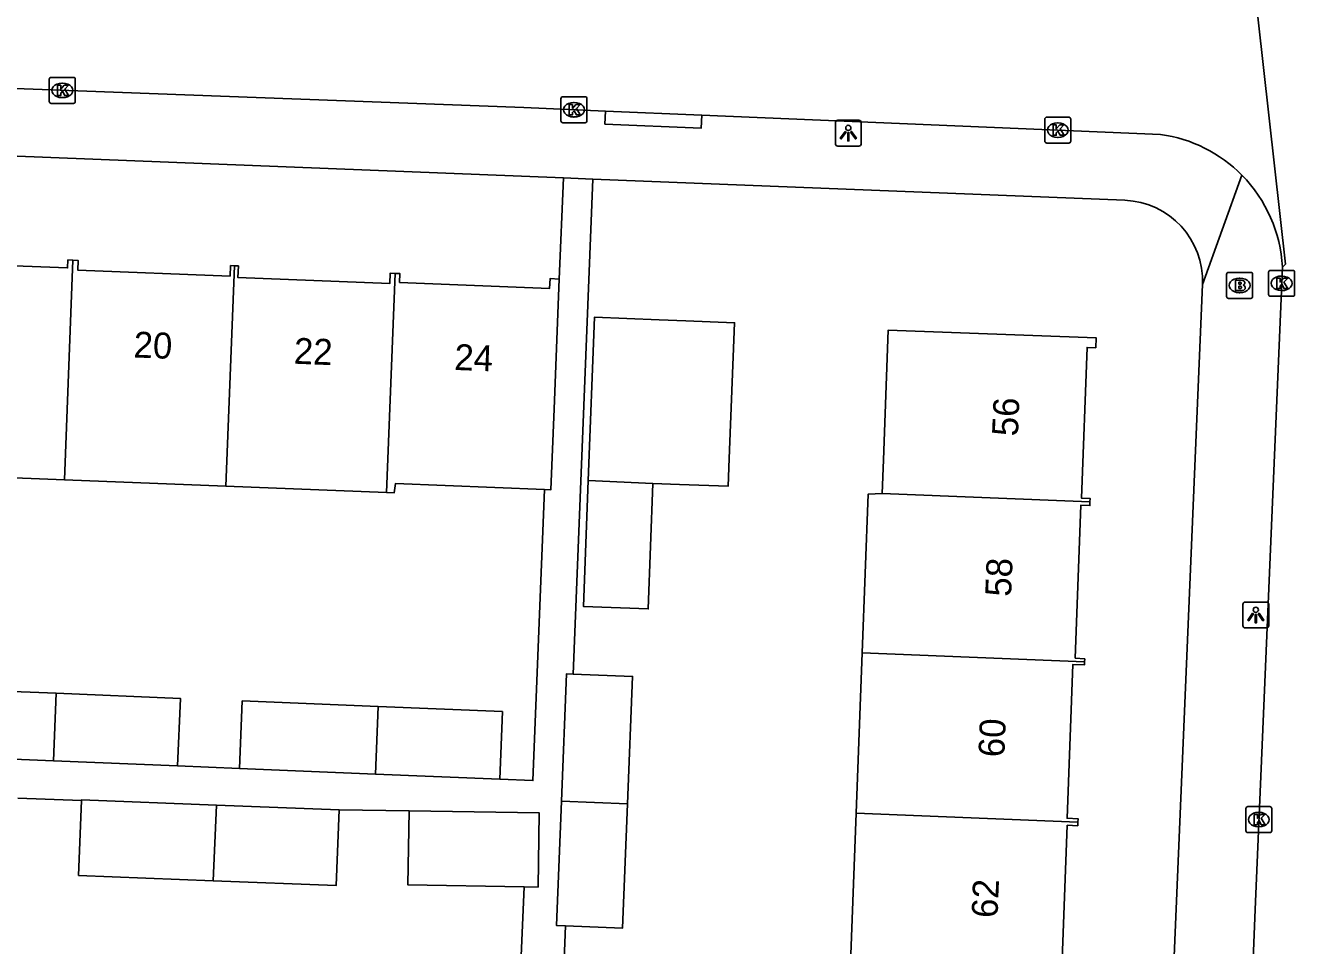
# Model space of a CAD drawing. Extents: x 160077 to 160945, y 386481 to 387498.
# Drawn here: x 160763.56 to 160812.48, y 386635.24 to 386670.7 of the extents above; entities that cross this region are included whole.
import ezdxf

# ---------------------------------------------------------------- set-up
doc = ezdxf.new("R2010")
doc.units = 0
for name, color, linetype in [('IMGEO_Brandkraan', 7, 'Continuous'), ('IMGEO_Kolk', 7, 'Continuous'), ('IMGEO_Lichtpunt', 7, 'Continuous'), ('IMGEO_Pand', 7, 'Continuous'), ('IMGEO_Pand_nummerreeks', 7, 'Continuous'), ('IMGEO_Rijbaan_lokaal_open', 7, 'Continuous'), ('IMGEO_Voetpad_open', 7, 'Continuous')]:
    doc.layers.add(name, color=color, linetype=linetype)

msp = doc.modelspace()

# ---------------------------------------------------------------- linework, layer by layer
at = {"layer": 'IMGEO_Brandkraan'}
for p, q in [((160809.863, 386660.258), (160809.863, 386661.11)), ((160809.938, 386661.184), (160810.79, 386661.184)), ((160810.864, 386661.11), (160810.864, 386660.258)), ((160810.351, 386660.964), (160810.376, 386660.964)), ((160810.79, 386660.184), (160809.938, 386660.184)), ((160810.374, 386660.404), (160810.349, 386660.404))]:
    msp.add_line(p, q, dxfattribs=at)
for points in [[(160809.863, 386660.258), (160809.863, 386661.11)], [(160809.938, 386661.184), (160810.79, 386661.184)], [(160810.864, 386661.11), (160810.864, 386660.258)], [(160810.211, 386660.884), (160810.211, 386660.484), (160810.424, 386660.484)], [(160810.442, 386660.884), (160810.211, 386660.884)], [(160810.39, 386660.803), (160810.336, 386660.803), (160810.336, 386660.727)], [(160810.336, 386660.727), (160810.389, 386660.727)], [(160810.398, 386660.651), (160810.336, 386660.651), (160810.336, 386660.57)], [(160810.336, 386660.57), (160810.398, 386660.57)], [(160810.79, 386660.184), (160809.938, 386660.184)]]:
    msp.add_lwpolyline(points, dxfattribs=at)
for centre, radius, start, end in [((160809.94, 386661.108), 0.0765, 91.552, 178.448), ((160809.94, 386661.108), 0.0765, 91.552, 178.448), ((160810.788, 386661.108), 0.0765, 1.552, 88.448), ((160810.788, 386661.108), 0.0765, 1.552, 88.448), ((160810.391, 386660.765), 0.0379, 267.8285, 90.9355), ((160810.399, 386660.61), 0.0404, 269.8759, 90.5077), ((160810.43, 386660.735), 0.251, 268.6676, 293.5347), ((160810.446, 386660.739), 0.145, 59.4692, 91.5367), ((160810.471, 386660.786), 0.0922, 285.5137, 58.1501), ((160810.476, 386660.594), 0.105, 301.3115, 78.989), ((160809.94, 386660.26), 0.0765, 181.552, 268.448), ((160809.94, 386660.26), 0.0765, 181.552, 268.448), ((160810.788, 386660.26), 0.0765, 271.552, 358.448), ((160810.788, 386660.26), 0.0765, 271.552, 358.448)]:
    msp.add_arc(centre, radius, start, end, dxfattribs=at)
for centre, major_axis, ratio, start_param, end_param in [((160810.35, 386660.684), (-0.387, 0.002), 0.722429, 4.712389, 7.853982), ((160810.375, 386660.684), (-0.39, 0.002), 0.717154, 1.570796, 4.712389)]:
    msp.add_ellipse(centre, major_axis=major_axis, ratio=ratio, start_param=start_param, end_param=end_param, dxfattribs=at)
at = {"layer": 'IMGEO_Kolk'}
for p, q in [((160764.486, 386667.773), (160764.486, 386668.625)), ((160764.561, 386668.699), (160765.413, 386668.699)), ((160764.974, 386668.479), (160764.999, 386668.479)), ((160765.487, 386668.625), (160765.487, 386667.773)), ((160764.997, 386667.919), (160764.972, 386667.919)), ((160784.207, 386667.027), (160784.207, 386667.879)), ((160784.282, 386667.953), (160785.134, 386667.953)), ((160785.208, 386667.879), (160785.208, 386667.027)), ((160765.413, 386667.699), (160764.561, 386667.699)), ((160784.695, 386667.733), (160784.72, 386667.733)), ((160785.134, 386666.953), (160784.282, 386666.953)), ((160784.718, 386667.173), (160784.693, 386667.173)), ((160802.855, 386666.241), (160802.855, 386667.093)), ((160802.93, 386667.167), (160803.782, 386667.167)), ((160803.343, 386666.947), (160803.368, 386666.947)), ((160803.856, 386667.093), (160803.856, 386666.241)), ((160803.366, 386666.387), (160803.341, 386666.387)), ((160803.782, 386666.167), (160802.93, 386666.167)), ((160811.482, 386660.338), (160811.482, 386661.19)), ((160811.557, 386661.264), (160812.409, 386661.264)), ((160811.97, 386661.044), (160811.995, 386661.044)), ((160812.483, 386661.19), (160812.483, 386660.338)), ((160812.409, 386660.264), (160811.557, 386660.264)), ((160811.993, 386660.484), (160811.968, 386660.484)), ((160810.603, 386639.674), (160810.603, 386640.526)), ((160810.678, 386640.6), (160811.53, 386640.6)), ((160811.604, 386640.526), (160811.604, 386639.674)), ((160811.091, 386640.38), (160811.116, 386640.38)), ((160811.53, 386639.6), (160810.678, 386639.6)), ((160811.114, 386639.82), (160811.089, 386639.82))]:
    msp.add_line(p, q, dxfattribs=at)
for points in [[(160764.486, 386667.773), (160764.486, 386668.625)], [(160764.561, 386668.699), (160765.413, 386668.699)], [(160764.807, 386668.399), (160764.93, 386668.399), (160764.93, 386668.248), (160765.06, 386668.399), (160765.224, 386668.399), (160765.078, 386668.248), (160765.231, 386667.999), (160765.079, 386667.999), (160764.994, 386668.163), (160764.93, 386668.096), (160764.93, 386667.999), (160764.807, 386667.999), (160764.807, 386668.399)], [(160765.487, 386668.625), (160765.487, 386667.773)], [(160784.207, 386667.027), (160784.207, 386667.879)], [(160784.282, 386667.953), (160785.134, 386667.953)], [(160785.208, 386667.879), (160785.208, 386667.027)], [(160765.413, 386667.699), (160764.561, 386667.699)], [(160784.528, 386667.653), (160784.651, 386667.653), (160784.651, 386667.502), (160784.781, 386667.653), (160784.945, 386667.653), (160784.799, 386667.502), (160784.952, 386667.253), (160784.8, 386667.253), (160784.715, 386667.417), (160784.651, 386667.35), (160784.651, 386667.253), (160784.528, 386667.253), (160784.528, 386667.653)], [(160785.134, 386666.953), (160784.282, 386666.953)], [(160802.855, 386666.241), (160802.855, 386667.093)], [(160802.93, 386667.167), (160803.782, 386667.167)], [(160803.176, 386666.867), (160803.299, 386666.867), (160803.299, 386666.716), (160803.429, 386666.867), (160803.593, 386666.867), (160803.447, 386666.716), (160803.6, 386666.467), (160803.448, 386666.467), (160803.363, 386666.631), (160803.299, 386666.564), (160803.299, 386666.467), (160803.176, 386666.467), (160803.176, 386666.867)], [(160803.856, 386667.093), (160803.856, 386666.241)], [(160803.782, 386666.167), (160802.93, 386666.167)], [(160811.482, 386660.338), (160811.482, 386661.19)], [(160811.557, 386661.264), (160812.409, 386661.264)], [(160812.483, 386661.19), (160812.483, 386660.338)], [(160811.803, 386660.964), (160811.926, 386660.964), (160811.926, 386660.813), (160812.056, 386660.964), (160812.22, 386660.964), (160812.074, 386660.813), (160812.227, 386660.564), (160812.075, 386660.564), (160811.99, 386660.728), (160811.926, 386660.661), (160811.926, 386660.564), (160811.803, 386660.564), (160811.803, 386660.964)], [(160812.409, 386660.264), (160811.557, 386660.264)], [(160810.603, 386639.674), (160810.603, 386640.526)], [(160810.678, 386640.6), (160811.53, 386640.6)], [(160811.604, 386640.526), (160811.604, 386639.674)], [(160810.924, 386640.3), (160811.047, 386640.3), (160811.047, 386640.149), (160811.177, 386640.3), (160811.341, 386640.3), (160811.195, 386640.149), (160811.348, 386639.9), (160811.196, 386639.9), (160811.111, 386640.064), (160811.047, 386639.997), (160811.047, 386639.9), (160810.924, 386639.9), (160810.924, 386640.3)], [(160811.53, 386639.6), (160810.678, 386639.6)]]:
    msp.add_lwpolyline(points, dxfattribs=at)
for centre, start, end in [((160764.563, 386668.623), 91.552, 178.448), ((160764.563, 386668.623), 91.552, 178.448), ((160765.411, 386668.623), 1.552, 88.448), ((160765.411, 386668.623), 1.552, 88.448), ((160784.284, 386667.877), 91.552, 178.448), ((160784.284, 386667.877), 91.552, 178.448), ((160785.132, 386667.877), 1.552, 88.448), ((160785.132, 386667.877), 1.552, 88.448), ((160764.563, 386667.775), 181.552, 268.448), ((160764.563, 386667.775), 181.552, 268.448), ((160765.411, 386667.775), 271.552, 358.448), ((160765.411, 386667.775), 271.552, 358.448), ((160784.284, 386667.029), 181.552, 268.448), ((160784.284, 386667.029), 181.552, 268.448), ((160785.132, 386667.029), 271.552, 358.448), ((160785.132, 386667.029), 271.552, 358.448), ((160802.932, 386667.091), 91.552, 178.448), ((160802.932, 386667.091), 91.552, 178.448), ((160803.78, 386667.091), 1.552, 88.448), ((160803.78, 386667.091), 1.552, 88.448), ((160802.932, 386666.243), 181.552, 268.448), ((160802.932, 386666.243), 181.552, 268.448), ((160803.78, 386666.243), 271.552, 358.448), ((160803.78, 386666.243), 271.552, 358.448), ((160811.559, 386661.188), 91.552, 178.448), ((160811.559, 386661.188), 91.552, 178.448), ((160812.407, 386661.188), 1.552, 88.448), ((160812.407, 386661.188), 1.552, 88.448), ((160811.559, 386660.34), 181.552, 268.448), ((160811.559, 386660.34), 181.552, 268.448), ((160812.407, 386660.34), 271.552, 358.448), ((160812.407, 386660.34), 271.552, 358.448), ((160810.68, 386640.524), 91.552, 178.448), ((160810.68, 386640.524), 91.552, 178.448), ((160811.528, 386640.524), 1.552, 88.448), ((160811.528, 386640.524), 1.552, 88.448), ((160810.68, 386639.676), 181.552, 268.448), ((160810.68, 386639.676), 181.552, 268.448), ((160811.528, 386639.676), 271.552, 358.448), ((160811.528, 386639.676), 271.552, 358.448)]:
    msp.add_arc(centre, 0.0765, start, end, dxfattribs=at)
for centre, major_axis, ratio, start_param, end_param in [((160764.973, 386668.199), (-0.387, 0.002), 0.722429, 4.712389, 7.853982), ((160764.998, 386668.199), (-0.39, 0.002), 0.717154, 1.570796, 4.712389), ((160784.694, 386667.453), (-0.387, 0.002), 0.722429, 4.712389, 7.853982), ((160784.719, 386667.453), (-0.39, 0.002), 0.717154, 1.570796, 4.712389), ((160803.342, 386666.667), (-0.387, 0.002), 0.722429, 4.712389, 7.853982), ((160803.367, 386666.667), (-0.39, 0.002), 0.717154, 1.570796, 4.712389), ((160811.969, 386660.764), (-0.387, 0.002), 0.722429, 4.712389, 7.853982), ((160811.994, 386660.764), (-0.39, 0.002), 0.717154, 1.570796, 4.712389), ((160811.09, 386640.1), (-0.387, 0.002), 0.722429, 4.712389, 7.853982), ((160811.115, 386640.1), (-0.39, 0.002), 0.717154, 1.570796, 4.712389)]:
    msp.add_ellipse(centre, major_axis=major_axis, ratio=ratio, start_param=start_param, end_param=end_param, dxfattribs=at)
at = {"layer": 'IMGEO_Lichtpunt'}
for p, q in [((160794.783, 386666.955), (160794.783, 386666.148)), ((160794.783, 386666.955), (160794.783, 386666.148)), ((160795.685, 386667.05), (160794.877, 386667.05)), ((160795.685, 386667.05), (160794.877, 386667.05)), ((160795.779, 386666.148), (160795.779, 386666.955)), ((160795.779, 386666.148), (160795.779, 386666.955)), ((160794.877, 386666.054), (160795.685, 386666.054)), ((160794.877, 386666.054), (160795.685, 386666.054)), ((160810.489, 386648.387), (160810.489, 386647.58)), ((160810.489, 386648.387), (160810.489, 386647.58)), ((160811.391, 386648.482), (160810.583, 386648.482)), ((160811.391, 386648.482), (160810.583, 386648.482)), ((160811.485, 386647.58), (160811.485, 386648.387)), ((160811.485, 386647.58), (160811.485, 386648.387)), ((160810.583, 386647.486), (160811.391, 386647.486)), ((160810.583, 386647.486), (160811.391, 386647.486))]:
    msp.add_line(p, q, dxfattribs=at)
for points in [[(160795.157, 386666.619), (160795.196, 386666.591), (160795.008, 386666.329), (160794.97, 386666.356), (160795.157, 386666.619)], [(160795.259, 386666.571), (160795.306, 386666.571), (160795.306, 386666.249), (160795.259, 386666.249), (160795.259, 386666.571)], [(160795.369, 386666.591), (160795.407, 386666.618), (160795.594, 386666.356), (160795.555, 386666.328), (160795.369, 386666.591)], [(160810.863, 386648.051), (160810.902, 386648.023), (160810.714, 386647.761), (160810.676, 386647.788), (160810.863, 386648.051)], [(160810.965, 386648.003), (160811.012, 386648.003), (160811.012, 386647.681), (160810.965, 386647.681), (160810.965, 386648.003)], [(160811.075, 386648.023), (160811.113, 386648.05), (160811.3, 386647.788), (160811.261, 386647.76), (160811.075, 386648.023)]]:
    msp.add_lwpolyline(points, dxfattribs=at)
for centre in [(160795.282, 386666.753), (160810.988, 386648.185)]:
    msp.add_circle(centre, 0.0994, dxfattribs=at)
for centre, start, end in [((160794.877, 386666.955), 90, 180), ((160794.877, 386666.955), 90, 180), ((160795.685, 386666.955), 0, 90), ((160795.685, 386666.955), 0, 90), ((160794.877, 386666.148), 180, 270), ((160794.877, 386666.148), 180, 270), ((160795.685, 386666.148), 270, 0), ((160795.685, 386666.148), 270, 360), ((160810.583, 386648.387), 90, 180), ((160810.583, 386648.387), 90, 180), ((160811.391, 386648.387), 0, 90), ((160811.391, 386648.387), 0, 90), ((160810.583, 386647.58), 180, 270), ((160810.583, 386647.58), 180, 270), ((160811.391, 386647.58), 270, 0), ((160811.391, 386647.58), 270, 360)]:
    msp.add_arc(centre, 0.0946, start, end, dxfattribs=at)
at = {"layer": 'IMGEO_Pand'}
for points in [[(160759.252, 386661.87), (160759.369, 386661.869), (160759.369, 386661.58), (160765.188, 386661.36), (160765.2, 386661.664), (160765.398, 386661.657)], [(160765.398, 386661.657), (160765.07, 386653.196)], [(160765.398, 386661.657), (160765.597, 386661.649), (160765.583, 386661.277), (160771.454, 386661.043), (160771.47, 386661.448), (160771.622, 386661.442)], [(160771.293, 386652.951), (160771.622, 386661.442)], [(160771.622, 386661.442), (160771.775, 386661.435), (160771.758, 386660.986), (160777.607, 386660.753), (160777.623, 386661.153), (160777.812, 386661.146)], [(160777.812, 386661.146), (160777.485, 386652.707)], [(160784.143, 386660.93), (160783.785, 386660.944), (160783.77, 386660.568), (160777.988, 386660.799), (160778.002, 386661.138), (160777.812, 386661.146)], [(160783.572, 386652.817), (160783.82, 386652.807), (160783.944, 386655.934), (160784.143, 386660.93)], [(160785.257, 386653.161), (160785.496, 386659.456), (160787.992, 386659.357), (160789.023, 386659.316), (160790.896, 386659.242), (160790.688, 386654.011), (160790.646, 386652.946), (160788.773, 386653.018), (160787.753, 386653.057)], [(160796.583, 386652.663), (160796.632, 386653.966), (160796.822, 386658.962), (160804.836, 386658.658), (160804.821, 386658.281), (160804.486, 386658.294), (160804.266, 386652.489), (160804.603, 386652.476), (160804.597, 386652.338)], [(160758.926, 386653.439), (160765.07, 386653.196)], [(160765.07, 386653.196), (160771.293, 386652.951)], [(160787.753, 386653.057), (160787.569, 386648.216), (160785.073, 386648.315), (160785.257, 386653.161)], [(160785.257, 386653.161), (160787.753, 386653.057)], [(160771.293, 386652.951), (160777.485, 386652.707)], [(160777.485, 386652.707), (160777.779, 386652.695), (160777.825, 386653.046), (160783.572, 386652.817)], [(160795.818, 386646.524), (160796.05, 386652.641), (160796.583, 386652.663)], [(160804.597, 386652.338), (160796.583, 386652.663)], [(160804.597, 386652.338), (160804.592, 386652.201), (160804.241, 386652.214), (160804.026, 386646.323), (160804.395, 386646.292), (160804.39, 386646.178)], [(160764.751, 386644.969), (160762.383, 386645.067), (160762.43, 386646.212), (160759.919, 386646.316), (160759.872, 386645.17), (160759.511, 386645.185), (160759.404, 386642.581)], [(160795.583, 386640.347), (160795.818, 386646.524)], [(160795.818, 386646.524), (160804.39, 386646.178)], [(160804.39, 386646.178), (160804.386, 386646.064), (160803.941, 386646.081), (160803.716, 386640.149), (160804.135, 386640.133), (160804.13, 386640)], [(160784.672, 386645.705), (160784.416, 386645.715), (160784.222, 386640.808)], [(160784.672, 386645.705), (160786.967, 386645.614), (160786.773, 386640.705)], [(160764.65, 386642.364), (160764.751, 386644.969)], [(160764.751, 386644.969), (160769.538, 386644.771), (160769.431, 386642.167)], [(160777.165, 386644.458), (160771.925, 386644.674), (160771.818, 386642.07)], [(160777.064, 386641.853), (160777.165, 386644.458)], [(160777.165, 386644.458), (160781.952, 386644.26), (160781.845, 386641.656)], [(160759.404, 386642.581), (160764.65, 386642.364)], [(160769.431, 386642.167), (160764.65, 386642.364)], [(160777.064, 386641.853), (160771.818, 386642.07)], [(160781.845, 386641.656), (160777.064, 386641.853)], [(160765.729, 386640.833), (160765.615, 386637.952), (160770.807, 386637.746)], [(160770.929, 386640.659), (160765.73, 386640.865), (160765.729, 386640.833)], [(160770.807, 386637.746), (160770.929, 386640.659)], [(160775.653, 386640.471), (160775.538, 386637.558), (160770.807, 386637.746)], [(160770.929, 386640.659), (160775.653, 386640.471)], [(160778.356, 386640.441), (160778.308, 386637.581), (160782.782, 386637.507)], [(160782.782, 386637.507), (160783.322, 386637.498), (160783.369, 386640.358), (160778.356, 386640.441)], [(160784.222, 386640.808), (160784.032, 386636.022), (160784.384, 386636.008)], [(160784.222, 386640.808), (160786.773, 386640.705)], [(160786.773, 386640.705), (160786.584, 386635.921), (160784.384, 386636.008)], [(160795.351, 386634.223), (160795.583, 386640.347)], [(160795.583, 386640.347), (160804.13, 386640)], [(160804.13, 386640), (160804.124, 386639.865), (160803.722, 386639.88), (160803.5, 386634.021), (160803.878, 386634.007), (160803.873, 386633.878)]]:
    msp.add_lwpolyline(points, dxfattribs=at)
at = {"layer": 'IMGEO_Rijbaan_lokaal_open'}
for points in [[(160812.011, 386661.39), (160812.135, 386661.504), (160810.008, 386680.46), (160809.921, 386680.44)], [(160785.921, 386667.402), (160782.779, 386667.534), (160755.601, 386668.55), (160732.207, 386669.443), (160709.41, 386670.37)], [(160785.921, 386667.402), (160789.637, 386667.245)], [(160807.317, 386666.5), (160789.637, 386667.245)], [(160810.118, 386615.402), (160810.958, 386636.637), (160812.011, 386661.39)]]:
    msp.add_lwpolyline(points, dxfattribs=at)
for centre, radius, start, end in [((160806.584, 386661.117), 5.433, 44.564, 82.2475), ((160806.582, 386661.114), 5.436, 2.905, 44.5625)]:
    msp.add_arc(centre, radius, start, end, dxfattribs=at)
at = {"layer": 'IMGEO_Voetpad_open'}
for points in [[(160710.106, 386667.774), (160784.298, 386664.825)], [(160789.637, 386667.245), (160789.616, 386666.746), (160785.9, 386666.903), (160785.921, 386667.402)], [(160808.932, 386660.717), (160810.455, 386664.929)], [(160784.143, 386660.93), (160784.298, 386664.825)], [(160784.298, 386664.825), (160785.43, 386664.78)], [(160785.43, 386664.78), (160784.672, 386645.705)], [(160785.43, 386664.78), (160805.936, 386663.965)], [(160808.932, 386660.717), (160807.05, 386615.957)], [(160783.572, 386652.817), (160783.125, 386641.603), (160781.845, 386641.656)], [(160771.818, 386642.07), (160769.431, 386642.167)], [(160763.269, 386640.93), (160765.729, 386640.833)], [(160775.653, 386640.471), (160778.356, 386640.441)], [(160782.782, 386637.507), (160782.415, 386628.96)], [(160784.384, 386636.008), (160783.785, 386620.893), (160783.537, 386614.798)]]:
    msp.add_lwpolyline(points, dxfattribs=at)
msp.add_arc((160805.808, 386660.841), 3.127, 357.7259, 87.6519, dxfattribs=at)

# ---------------------------------------------------------------- texts
at = {"layer": 'IMGEO_Pand_nummerreeks'}
for s, rotation, p in [('20', 357.7745, (160767.721, 386657.909)), ('22', 357.7745, (160773.898, 386657.668)), ('24', 357.7769, (160780.084, 386657.428)), ('56', 87.571, (160801.817, 386654.859)), ('58', 87.571, (160801.554, 386648.676)), ('60', 87.571, (160801.292, 386642.489)), ('62', 87.571, (160801.029, 386636.297))]:
    msp.add_text(s, height=1, rotation=rotation, dxfattribs=at).set_placement(p)

doc.saveas('drawing.dxf')
